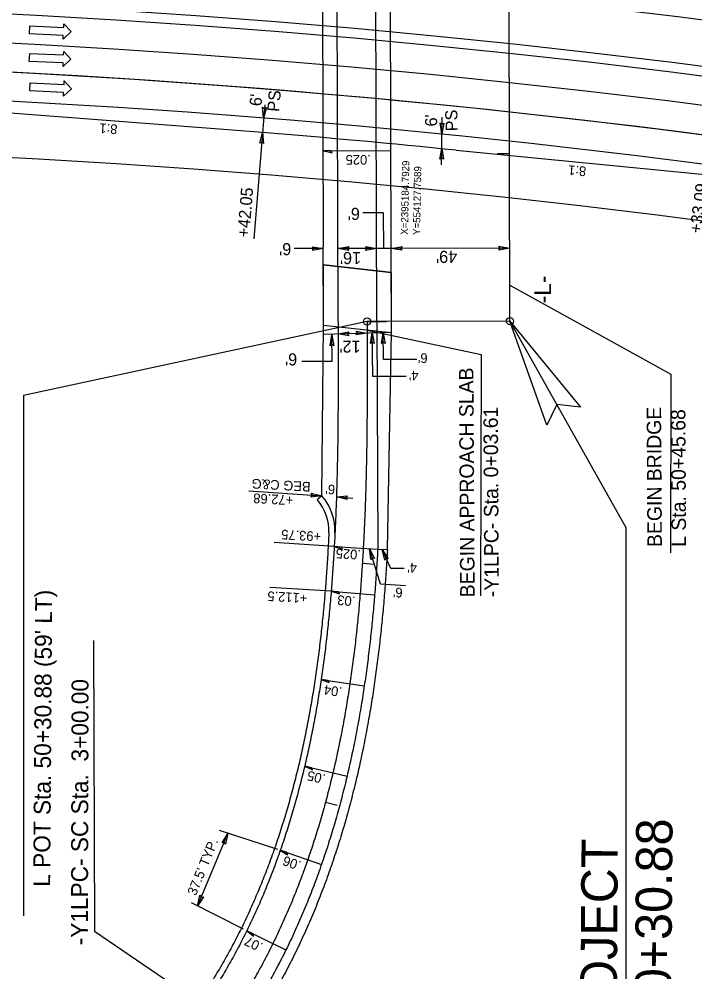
# Model space of a CAD drawing. Extents: x 2389694 to 2405615, y 547005 to 573532.
# Drawn here: x 2395029.1 to 2395308.3, y 553830.9 to 554224.7 of the extents above; entities that cross this region are included whole.
import ezdxf

# ---------------------------------------------------------------- set-up
doc = ezdxf.new("R2010")
doc.units = 0
for name, color, linetype in [('Old_Level_11', 7, 'Continuous'), ('Old_Level_22', 7, 'Continuous'), ('Prop Approach Slab', 7, 'Continuous'), ('Prop Approach Slab Hatching', 7, 'Continuous'), ('Prop Conc 2ft 6in Curb and Gutter', 7, 'Continuous'), ('Prop Dimension', 7, 'Continuous'), ('Prop Dimension Text', 7, 'Continuous'), ('Prop DSN Text', 7, 'Continuous'), ('Prop EOT', 7, 'Continuous'), ('Prop Horizontal Alignment', 7, 'Continuous'), ('Prop Horizontal Alignment Curve and Spiral Data', 7, 'Continuous'), ('Prop Horizontal Alignment Tick Large', 7, 'Continuous'), ('Prop Horizontal Alignment Tick Small', 7, 'Continuous'), ('Prop Lane Arrow Through CELL', 7, 'Continuous'), ('Prop Lane Lines', 7, 'Continuous'), ('Prop Super Arrow 1 Lane CELL', 7, 'Continuous'), ('Prop Superelevation Label', 7, 'Continuous')]:
    doc.layers.add(name, color=color, linetype=linetype)

msp = doc.modelspace()

# ---------------------------------------------------------------- linework, layer by layer
at = {"layer": 'Old_Level_22'}
for p, q in [((2395231.86, 554099.89), (2395279.7, 554014.59)), ((2395279.7, 554014.59), (2395279.71, 553656.75))]:
    msp.add_line(p, q, dxfattribs=at)
at = {"layer": 'Prop Approach Slab'}
for p, q in [((2395154.17, 554362.65), (2395154.78, 554130.56)), ((2395182.79, 554127.29), (2395182.18, 554359.37)), ((2395154.87, 554098.08), (2395154.78, 554130.56)), ((2395182.88, 554095.26), (2395182.79, 554127.29)), ((2395182.81, 554120.03), (2395154.8, 554123.08))]:
    msp.add_line(p, q, dxfattribs=at)
at = {"layer": 'Prop Approach Slab Hatching'}
msp.add_lwpolyline([(2395154.8, 554123.08), (2395182.81, 554120.03), (2395182.87, 554095.03), (2395154.87, 554098.08)], close=True, dxfattribs=at)
at = {"layer": 'Prop Conc 2ft 6in Curb and Gutter'}
msp.add_line((2395154.21, 554027.64), (2395152.31, 554026.02), dxfattribs=at)
for centre, radius, start, end in [((2394908.45, 553950.81), 235.5, 111.6201, 325.7741), ((2395137.11, 554013.02), 20, 358.0934, 40.5119)]:
    msp.add_arc(centre, radius, start, end, dxfattribs=at)
msp.add_spline([(2395157.09, 554012.36), (2395157.04, 554011.29), (2395156.83, 554007.32), (2395156.6, 554003.34), (2395156.35, 553999.38), (2395156.08, 553995.41), (2395155.78, 553991.45), (2395155.46, 553987.5), (2395155.12, 553983.55), (2395154.76, 553979.61), (2395154.36, 553975.67), (2395153.95, 553971.74), (2395153.5, 553967.81), (2395153.03, 553963.89), (2395152.52, 553959.98), (2395151.99, 553956.08), (2395151.43, 553952.18), (2395150.83, 553948.29), (2395150.21, 553944.41), (2395149.55, 553940.53), (2395148.86, 553936.67), (2395148.13, 553932.81), (2395147.37, 553928.97), (2395146.58, 553925.14), (2395145.75, 553921.31), (2395144.88, 553917.5), (2395143.97, 553913.7), (2395143.02, 553909.91), (2395142.04, 553906.14), (2395141.02, 553902.38), (2395139.95, 553898.64), (2395138.85, 553894.91), (2395137.7, 553891.19), (2395136.51, 553887.49), (2395135.28, 553883.81), (2395134.01, 553880.15), (2395132.69, 553876.51), (2395131.33, 553872.88), (2395129.92, 553869.28), (2395128.47, 553865.7), (2395126.97, 553862.14), (2395125.42, 553858.6), (2395123.83, 553855.09), (2395122.2, 553851.6), (2395120.51, 553848.14), (2395118.78, 553844.71), (2395117, 553841.31), (2395115.17, 553837.93), (2395113.29, 553834.58), (2395111.36, 553831.27), (2395109.39, 553827.99), (2395107.36, 553824.74), (2395105.29, 553821.53), (2395103.1, 553818.26)], degree=3, dxfattribs=at)
at = {"layer": 'Prop Dimension'}
for p, q in [((2395231.86, 554099.89), (2395231.19, 554355.88)), ((2395203.76, 554177.27), (2395203.83, 554184.18)), ((2395203.72, 554171.29), (2395203.76, 554177.27)), ((2395203.66, 554164.49), (2395203.72, 554171.29)), ((2395179.58, 554144.7), (2395171.15, 554144.66)), ((2395179.81, 554130.09), (2395179.58, 554144.7)), ((2395154.78, 554129.87), (2395142.75, 554129.84)), ((2395176.78, 554129.93), (2395160.78, 554129.89)), ((2395182.78, 554129.94), (2395172.78, 554129.92)), ((2395231.78, 554130.07), (2395182.78, 554129.94)), ((2395231.82, 554114.69), (2395298.34, 554077.96)), ((2395231.86, 554099.89), (2395172.86, 554099.73)), ((2395154.88, 554094.44), (2395182.88, 554095.26)), ((2395158.48, 554083.13), (2395158.32, 554094.16)), ((2395172.87, 554096.12), (2395219.92, 554086.07)), ((2395175.2, 554076.97), (2395174.95, 554095.09)), ((2395179.63, 554084.08), (2395179.48, 554095.1)), ((2395219.92, 554086.07), (2395219.66, 553986.33)), ((2395158.48, 554083.13), (2395145.93, 554083.15)), ((2395193.42, 554084.05), (2395179.63, 554084.08)), ((2395298.34, 554077.96), (2395298.15, 554004.14)), ((2395189, 554076.94), (2395175.2, 554076.97)), ((2395124.05, 554029.79), (2395154.21, 554027.64)), ((2395160.21, 554027.21), (2395167.03, 554026.73)), ((2395159.3, 554006.68), (2395134.46, 554008.34)), ((2395178.45, 553991.14), (2395173.84, 554005.86)), ((2395177.27, 554005.67), (2395181.27, 554005.45)), ((2395182.64, 553997.61), (2395179.1, 554005.52)), ((2395188.23, 553997.6), (2395182.64, 553997.61)), ((2395188.67, 553990.43), (2395178.45, 553991.14)), ((2395158.04, 553988.28), (2395132.74, 553989.77)), ((2395102.82, 553858.12), (2395115.41, 553888.15)), ((2395136, 553881.47), (2395111.88, 553889.3)), ((2395121.87, 553848.56), (2395100.3, 553859.38))]:
    msp.add_line(p, q, dxfattribs=at)
msp.add_lwpolyline([(2395231.68, 554169.01), (2395231.51, 554231.96), (2395231.27, 554231.96)], dxfattribs=at)
for points in [[(2395131.27, 554188.21), (2395130.14, 554183.79), (2395129.7, 554188.36), (2395130.45, 554187.72)], [(2395204.58, 554181.76), (2395203.76, 554177.27), (2395203.01, 554181.8), (2395203.8, 554181.22)], [(2395128.52, 554173.38), (2395129.66, 554177.8), (2395130.09, 554173.23), (2395129.34, 554173.87)], [(2395202.9, 554166.8), (2395203.72, 554171.29), (2395204.48, 554166.76), (2395203.69, 554167.34)], [(2395150.28, 554130.63), (2395154.78, 554129.87), (2395150.26, 554129.06), (2395150.83, 554129.86)], [(2395165.29, 554129.12), (2395160.78, 554129.89), (2395165.31, 554130.7), (2395164.73, 554129.9)], [(2395172.28, 554130.69), (2395176.78, 554129.93), (2395172.26, 554129.12), (2395172.83, 554129.92)], [(2395187.29, 554129.18), (2395182.78, 554129.94), (2395187.31, 554130.76), (2395186.73, 554129.95)], [(2395227.28, 554130.84), (2395231.78, 554130.07), (2395227.26, 554129.26), (2395227.83, 554130.06)], [(2395247.12, 554056.85), (2395231.86, 554099.89), (2395260.98, 554064.33), (2395251.19, 554065.44)], [(2395247.12, 554056.85), (2395231.86, 554099.89), (2395260.98, 554064.33), (2395251.19, 554065.44)], [(2395157.61, 554089.65), (2395158.32, 554094.16), (2395159.19, 554089.64), (2395158.38, 554090.21)], [(2395165.3, 554093.85), (2395160.8, 554094.62), (2395165.32, 554095.43), (2395164.75, 554094.63)], [(2395168.29, 554095.73), (2395172.79, 554094.96), (2395168.27, 554094.15), (2395168.84, 554094.95)], [(2395174.23, 554090.58), (2395174.95, 554095.09), (2395175.81, 554090.58), (2395175, 554091.14)], [(2395178.77, 554090.59), (2395179.48, 554095.1), (2395180.34, 554090.59), (2395179.53, 554091.15)], [(2395149.78, 554028.73), (2395154.21, 554027.64), (2395149.64, 554027.16), (2395150.27, 554027.92)], [(2395164.65, 554026.12), (2395160.21, 554027.21), (2395164.78, 554027.69), (2395164.15, 554026.93)], [(2395174.45, 554001.34), (2395173.84, 554005.86), (2395175.96, 554001.79), (2395175.02, 554002.09)], [(2395180.17, 554001.08), (2395179.1, 554005.52), (2395181.63, 554001.69), (2395180.66, 554001.9)], [(2395112.97, 553884.3), (2395115.41, 553888.15), (2395114.41, 553883.67), (2395113.89, 553884.51)], [(2395105.27, 553861.97), (2395102.82, 553858.12), (2395103.82, 553862.6), (2395104.34, 553861.76)]]:
    msp.add_lwpolyline(points, close=True, dxfattribs=at)
msp.add_arc((2394828.31, 550434.92), 3737.71, 73.27853, 89.01084, dxfattribs=at)
at = {"layer": 'Prop DSN Text'}
msp.add_line((2395130.58, 554189.23), (2395126.12, 554133.83), dxfattribs=at)
at = {"layer": 'Prop EOT'}
for p, q in [((2395160.86, 554099.7), (2395158.69, 554921.89)), ((2395176.86, 554099.74), (2395176.26, 554329.14)), ((2395129.66, 554177.8), (2394992.08, 554188.34)), ((2395209.68, 554170.5), (2395316.65, 554160.04)), ((2395154.21, 554027.64), (2395154.91, 554098.07)), ((2395176.86, 554099.74), (2395177.27, 554005.66)), ((2395181.27, 554005.45), (2395182.88, 554095.26))]:
    msp.add_line(p, q, dxfattribs=at)
for centre, radius, start, end in [((2394865.6, 554590.75), 1087, 256.52302, 12.63033), ((2394865.6, 554590.75), 1063, 256.52302, 12.63033), ((2394828.31, 550434.92), 3879, 67.475, 106.78848), ((2394828.31, 550434.92), 3867, 59.69891, 109.59769), ((2394828.31, 550434.92), 3843, 59.69891, 123.9393), ((2394828.31, 550434.92), 3839, 59.69891, 123.9393), ((2394828.31, 550434.92), 3801, 59.69891, 123.9393), ((2394828.31, 550434.92), 3797, 59.69891, 123.9393), ((2394828.31, 550434.92), 3761, 73.27853, 87.18326), ((2394908.45, 553950.81), 256, 111.6201, 325.7741), ((2394908.45, 553950.81), 260, 116.4784, 325.7741), ((2394828.31, 550434.92), 3755, 84.17087, 85.39696), ((2394908.45, 553950.81), 238, 111.6201, 325.7741), ((2395137.11, 554013.02), 22.5, 358.0934, 40.5115)]:
    msp.add_arc(centre, radius, start, end, dxfattribs=at)
for points in [[(2395160.86, 554099.7), (2395160.87, 554095.65), (2395160.88, 554091.6), (2395160.89, 554087.55), (2395160.9, 554083.5), (2395160.9, 554079.46), (2395160.9, 554075.42), (2395160.89, 554071.38), (2395160.87, 554067.35), (2395160.85, 554063.32), (2395160.82, 554059.29), (2395160.79, 554055.26), (2395160.74, 554051.24), (2395160.68, 554047.22), (2395160.61, 554043.2), (2395160.53, 554039.19), (2395160.43, 554035.17), (2395160.32, 554031.16), (2395160.2, 554027.16), (2395160.06, 554023.16), (2395159.9, 554019.16), (2395159.73, 554015.16), (2395159.54, 554011.17), (2395159.33, 554007.18), (2395159.1, 554003.19), (2395158.84, 553999.21), (2395158.57, 553995.23), (2395158.28, 553991.26), (2395157.96, 553987.29), (2395157.61, 553983.33), (2395157.25, 553979.37), (2395156.85, 553975.41), (2395156.43, 553971.46), (2395155.98, 553967.52), (2395155.51, 553963.58), (2395155, 553959.65), (2395154.47, 553955.73), (2395153.9, 553951.81), (2395153.3, 553947.9), (2395152.68, 553944), (2395152.01, 553940.1), (2395151.32, 553936.22), (2395150.59, 553932.34), (2395149.82, 553928.47), (2395149.02, 553924.62), (2395148.19, 553920.77), (2395147.31, 553916.93), (2395146.4, 553913.11), (2395145.45, 553909.3), (2395144.46, 553905.5), (2395143.43, 553901.71), (2395142.35, 553897.94), (2395141.24, 553894.18), (2395140.09, 553890.44), (2395138.89, 553886.71), (2395137.65, 553883.01), (2395136.36, 553879.31), (2395135.03, 553875.64), (2395133.66, 553871.99), (2395132.24, 553868.36), (2395130.78, 553864.74), (2395129.27, 553861.15), (2395127.71, 553857.59), (2395126.1, 553854.04), (2395124.45, 553850.53), (2395122.75, 553847.03), (2395121, 553843.57), (2395119.2, 553840.13), (2395117.36, 553836.72), (2395115.46, 553833.34), (2395113.51, 553830), (2395111.52, 553826.68), (2395109.47, 553823.4), (2395107.38, 553820.16), (2395105.18, 553816.87)], [(2395177.27, 554005.67), (2395177.06, 554002.1), (2395176.81, 553998.03), (2395176.53, 553993.95), (2395176.22, 553989.87), (2395175.89, 553985.79), (2395175.54, 553981.72), (2395175.16, 553977.64), (2395174.76, 553973.57), (2395174.32, 553969.49), (2395173.86, 553965.42), (2395173.37, 553961.36), (2395172.85, 553957.29), (2395172.29, 553953.23), (2395171.71, 553949.17), (2395171.09, 553945.11), (2395170.43, 553941.06), (2395169.75, 553937.01), (2395169.02, 553932.97), (2395168.26, 553928.93), (2395167.47, 553924.9), (2395166.63, 553920.87), (2395165.75, 553916.85), (2395164.84, 553912.84), (2395163.89, 553908.84), (2395162.89, 553904.85), (2395161.85, 553900.86), (2395160.77, 553896.89), (2395159.64, 553892.92), (2395158.47, 553888.97), (2395157.25, 553885.03), (2395155.99, 553881.1), (2395154.68, 553877.19), (2395153.33, 553873.29), (2395151.92, 553869.41), (2395150.47, 553865.55), (2395148.97, 553861.7), (2395147.41, 553857.87), (2395145.81, 553854.06), (2395144.16, 553850.27), (2395142.45, 553846.5), (2395140.69, 553842.76), (2395138.88, 553839.04), (2395137.01, 553835.34), (2395135.09, 553831.67), (2395133.12, 553828.03), (2395131.09, 553824.42), (2395129.01, 553820.83), (2395126.87, 553817.28), (2395124.67, 553813.76), (2395122.42, 553810.27), (2395120.14, 553806.86)], [(2395181.27, 554005.45), (2395181.06, 554001.86), (2395180.8, 553997.76), (2395180.52, 553993.66), (2395180.21, 553989.56), (2395179.88, 553985.46), (2395179.53, 553981.36), (2395179.14, 553977.26), (2395178.74, 553973.16), (2395178.3, 553969.06), (2395177.83, 553964.96), (2395177.34, 553960.86), (2395176.81, 553956.76), (2395176.25, 553952.67), (2395175.66, 553948.58), (2395175.04, 553944.49), (2395174.38, 553940.4), (2395173.69, 553936.32), (2395172.96, 553932.24), (2395172.19, 553928.17), (2395171.39, 553924.1), (2395170.54, 553920.04), (2395169.66, 553915.98), (2395168.74, 553911.93), (2395167.77, 553907.89), (2395166.76, 553903.86), (2395165.71, 553899.83), (2395164.62, 553895.82), (2395163.48, 553891.81), (2395162.3, 553887.81), (2395161.07, 553883.83), (2395159.79, 553879.86), (2395158.47, 553875.9), (2395157.1, 553871.96), (2395155.68, 553868.03), (2395154.2, 553864.12), (2395152.68, 553860.22), (2395151.11, 553856.34), (2395149.49, 553852.48), (2395147.81, 553848.65), (2395146.08, 553844.83), (2395144.3, 553841.03), (2395142.46, 553837.26), (2395140.57, 553833.51), (2395138.62, 553829.79), (2395136.62, 553826.1), (2395134.56, 553822.43), (2395132.45, 553818.79), (2395130.28, 553815.19), (2395128.05, 553811.62), (2395125.77, 553808.08), (2395123.47, 553804.64)]]:
    msp.add_spline(points, degree=3, dxfattribs=at)
at = {"layer": 'Prop Horizontal Alignment'}
msp.add_line((2395231.86, 554099.89), (2395228.72, 555288.08), dxfattribs=at)
for centre, radius, start, end in [((2394865.6, 554590.75), 1075, 256.52302, 12.63033), ((2394828.31, 550434.92), 3820, 59.69891, 123.9393), ((2394908.45, 553950.81), 250, 111.6201, 325.7741)]:
    msp.add_arc(centre, radius, start, end, dxfattribs=at)
msp.add_spline([(2395172.86, 554099.73), (2395172.87, 554095.68), (2395172.88, 554091.62), (2395172.89, 554087.57), (2395172.9, 554083.51), (2395172.9, 554079.46), (2395172.9, 554075.41), (2395172.89, 554071.35), (2395172.87, 554067.3), (2395172.85, 554063.24), (2395172.82, 554059.19), (2395172.78, 554055.14), (2395172.74, 554051.08), (2395172.68, 554047.03), (2395172.61, 554042.97), (2395172.52, 554038.92), (2395172.43, 554034.87), (2395172.32, 554030.82), (2395172.19, 554026.76), (2395172.05, 554022.71), (2395171.89, 554018.66), (2395171.72, 554014.61), (2395171.52, 554010.56), (2395171.31, 554006.51), (2395171.07, 554002.47), (2395170.82, 553998.42), (2395170.54, 553994.38), (2395170.24, 553990.33), (2395169.91, 553986.29), (2395169.57, 553982.25), (2395169.19, 553978.22), (2395168.79, 553974.18), (2395168.36, 553970.15), (2395167.9, 553966.12), (2395167.41, 553962.1), (2395166.9, 553958.08), (2395166.35, 553954.06), (2395165.77, 553950.05), (2395165.16, 553946.04), (2395164.51, 553942.04), (2395163.84, 553938.04), (2395163.12, 553934.05), (2395162.37, 553930.07), (2395161.58, 553926.09), (2395160.76, 553922.12), (2395159.9, 553918.16), (2395159, 553914.21), (2395158.06, 553910.26), (2395157.07, 553906.33), (2395156.05, 553902.41), (2395154.99, 553898.49), (2395153.88, 553894.59), (2395152.73, 553890.71), (2395151.53, 553886.83), (2395150.29, 553882.97), (2395149, 553879.13), (2395147.67, 553875.3), (2395146.29, 553871.49), (2395144.87, 553867.69), (2395143.39, 553863.92), (2395141.87, 553860.16), (2395140.3, 553856.42), (2395138.67, 553852.71), (2395137, 553849.02), (2395135.28, 553845.35), (2395133.5, 553841.7), (2395131.67, 553838.08), (2395129.8, 553834.49), (2395127.86, 553830.93), (2395125.88, 553827.39), (2395123.84, 553823.89), (2395121.75, 553820.41), (2395119.61, 553816.97), (2395117.41, 553813.57), (2395115.15, 553810.2)], degree=3, dxfattribs=at)
at = {"layer": 'Prop Horizontal Alignment Curve and Spiral Data'}
for p, q in [((2395172.86, 554099.73), (2395030.9, 554069.18)), ((2395030.9, 554069.18), (2395030.9, 553854.06)), ((2395059.86, 553967.91), (2395060.25, 553847.54)), ((2395113.91, 553811.04), (2395060.25, 553847.54))]:
    msp.add_line(p, q, dxfattribs=at)
for centre in [(2395172.86, 554099.73), (2395231.86, 554099.89)]:
    msp.add_circle(centre, 1.5, dxfattribs=at)
at = {"layer": 'Prop Horizontal Alignment Tick Large'}
msp.add_line((2395172.86, 554099.73), (2395180.86, 554099.75), dxfattribs=at)
at = {"layer": 'Prop Horizontal Alignment Tick Small'}
for p, q in [((2395231.68, 554169.01), (2395226.68, 554169)), ((2395170.91, 553999.77), (2395175.9, 553999.45)), ((2395155.7, 553901.1), (2395160.53, 553899.8))]:
    msp.add_line(p, q, dxfattribs=at)
at = {"layer": 'Prop Lane Arrow Through CELL'}
for p, q in [((2395033.41, 554218.62), (2395033.56, 554221.92)), ((2395033.56, 554221.92), (2395047.55, 554221.28)), ((2395050.62, 554219.54), (2395047.33, 554216.48)), ((2395047.55, 554221.28), (2395047.62, 554222.78)), ((2395047.62, 554222.78), (2395050.62, 554219.54)), ((2395047.4, 554217.98), (2395033.41, 554218.62)), ((2395047.33, 554216.48), (2395047.4, 554217.98)), ((2395047.5, 554209.87), (2395047.57, 554211.37)), ((2395047.57, 554211.37), (2395050.57, 554208.13)), ((2395033.36, 554207.21), (2395033.51, 554210.51)), ((2395047.35, 554206.57), (2395033.36, 554207.21)), ((2395033.51, 554210.51), (2395047.5, 554209.87)), ((2395050.57, 554208.13), (2395047.28, 554205.07)), ((2395047.28, 554205.07), (2395047.35, 554206.57)), ((2395033.56, 554195.03), (2395033.71, 554198.32)), ((2395033.71, 554198.32), (2395047.69, 554197.69)), ((2395050.77, 554195.94), (2395047.47, 554192.89)), ((2395047.69, 554197.69), (2395047.76, 554199.18)), ((2395047.76, 554199.18), (2395050.77, 554195.94)), ((2395047.54, 554194.39), (2395033.56, 554195.03)), ((2395047.47, 554192.89), (2395047.54, 554194.39))]:
    msp.add_line(p, q, dxfattribs=at)
at = {"layer": 'Prop Lane Lines'}
for radius, start, end in [(3855, 59.69891, 123.9393), (3785, 59.69891, 123.9393), (3773, 68.81433, 89.07696), (3773, 59.69891, 88.86914)]:
    msp.add_arc((2394828.31, 550434.92), radius, start, end, dxfattribs=at)
at = {"layer": 'Prop Super Arrow 1 Lane CELL'}
for p, q in [((2395154.93, 554170.27), (2395182.68, 554170.34)), ((2395159.3, 554006.68), (2395177.11, 554005.68)), ((2395158.04, 553988.28), (2395175.98, 553986.81)), ((2395153.9, 553951.81), (2395171.71, 553949.17)), ((2395147.09, 553915.98), (2395164.6, 553911.84)), ((2395137.01, 553881.16), (2395154.01, 553875.24)), ((2395123.18, 553847.9), (2395139.33, 553839.97))]:
    msp.add_line(p, q, dxfattribs=at)
for points in [[(2395154.93, 554170.27), (2395158.43, 554169.47), (2395157.88, 554170.27)], [(2395159.3, 554006.68), (2395162.75, 554005.68), (2395162.25, 554006.51)], [(2395158.04, 553988.28), (2395161.46, 553987.2), (2395160.98, 553988.04)], [(2395153.9, 553951.81), (2395157.25, 553950.5), (2395156.82, 553951.38)], [(2395147.09, 553915.98), (2395150.31, 553914.39), (2395149.96, 553915.3)], [(2395137.01, 553881.16), (2395140.05, 553879.25), (2395139.8, 553880.19)], [(2395123.18, 553847.9), (2395125.97, 553845.64), (2395125.83, 553846.6)]]:
    msp.add_lwpolyline(points, close=True, dxfattribs=at)

# ---------------------------------------------------------------- texts
at = {"layer": 'Old_Level_11'}
for s, height, rotation, p in [('BEGIN BRIDGE', 6, 90.3233, (2395294.63, 554006.53)), ('L Sta. 50+45.68', 6, 90.3233, (2395304.63, 554006.59)), ('BEG C&G', 4, 176.7944, (2395149.62, 554033.36)), ('+72.68', 4, 176.7944, (2395142.45, 554027.75))]:
    msp.add_text(s, height=height, rotation=rotation, dxfattribs=at).set_placement(p)
at = {"layer": 'Old_Level_22'}
for s, p in [('R-2719A -L- Sta. 50+30.88', (2395297.3, 553653.98)), ('BEGIN STATE PROJECT ', (2395274.8, 553654.14))]:
    msp.add_text(s, height=15, rotation=89.5902, dxfattribs=at).set_placement(p)
at = {"layer": 'Prop Dimension'}
for s, p in [('X=2395184.7929', (2395189.77, 554135.54)), ('Y=554127.7589', (2395194.76, 554135.45))]:
    msp.add_text(s, height=3, rotation=88.9494, dxfattribs=at).set_placement(p)
at = {"layer": 'Prop Dimension Text'}
for s, height, rotation, p in [("6'", 5, 91.7686, (2395201.87, 554180.4)), ('PS', 5, 91.7686, (2395210.36, 554178.42)), ('8:1', 4, 175.3625, (2395069.89, 554181.06)), ('8:1', 4, 175.3625, (2395263.5, 554163.7)), ("6'", 5, 179.9879, (2395169.9, 554146.68)), ("6'", 5, 179.9879, (2395141.56, 554132.12)), ("16'", 5, 179.9879, (2395170.38, 554128.44)), ("49'", 5, 179.9879, (2395210.09, 554128.95)), ("12'", 5, 179.9879, (2395170.19, 554091.85)), ("6'", 5, 179.9879, (2395144, 554086.56)), ("6'", 4, 179.7599, (2395197.88, 554086.57)), ("4'", 4, 179.7599, (2395194.13, 554079.36)), ('BEGIN APPROACH SLAB', 6, 90.3233, (2395217.31, 553985.75)), ('-Y1LPC- Sta. 0+03.61', 6, 90.3233, (2395227.3, 553985.81)), ("6'", 4, 176.7944, (2395159.77, 554032.2)), ('+93.75', 4, 176.7944, (2395153.98, 554012.77)), ("4'", 4, 179.7599, (2395193.48, 553999.88)), ('+112.5', 4, 176.7944, (2395148.28, 553987.29)), ("6'", 4, 179.7599, (2395187.55, 553989.66)), ("37.5' TYP.", 4, 67.8603, (2395102.14, 553862.13))]:
    msp.add_text(s, height=height, rotation=rotation, dxfattribs=at).set_placement(p)
at = {"layer": 'Prop DSN Text'}
for s, rotation, p in [("6'", 85.397, (2395129.24, 554188.57)), ('PS', 85.397, (2395136.57, 554186.24)), ('+33.09', 82.2817, (2395310.87, 554135.98)), ('+42.05', 85.397, (2395124.17, 554134.33))]:
    msp.add_text(s, height=5, rotation=rotation, dxfattribs=at).set_placement(p)
at = {"layer": 'Prop Horizontal Alignment Curve and Spiral Data'}
for s, rotation, p in [('-L-', 90, (2395248.88, 554107.24)), ("L POT Sta. 50+30.88 (59' LT)", 89.5902, (2395041.94, 553866.07)), ('-Y1LPC- SC Sta.  3+00.00', 89.8665, (2395057.56, 553841.89))]:
    msp.add_text(s, height=7, rotation=rotation, dxfattribs=at).set_placement(p)
at = {"layer": 'Prop Superelevation Label'}
for s, rotation, p in [('.025', 180.1515, (2395174.4, 554168.55)), ('.025', 176.7944, (2395170.43, 554005.28)), ('.03', 175.3172, (2395168.14, 553985.97)), ('.04', 171.5572, (2395162.72, 553948.45)), ('.05', 166.7228, (2395155.93, 553912.4)), ('.06', 160.8142, (2395145.95, 553876.5)), ('.07', 153.8313, (2395130.21, 553842.54))]:
    msp.add_text(s, height=4, rotation=rotation, dxfattribs=at).set_placement(p)

doc.saveas('drawing.dxf')
